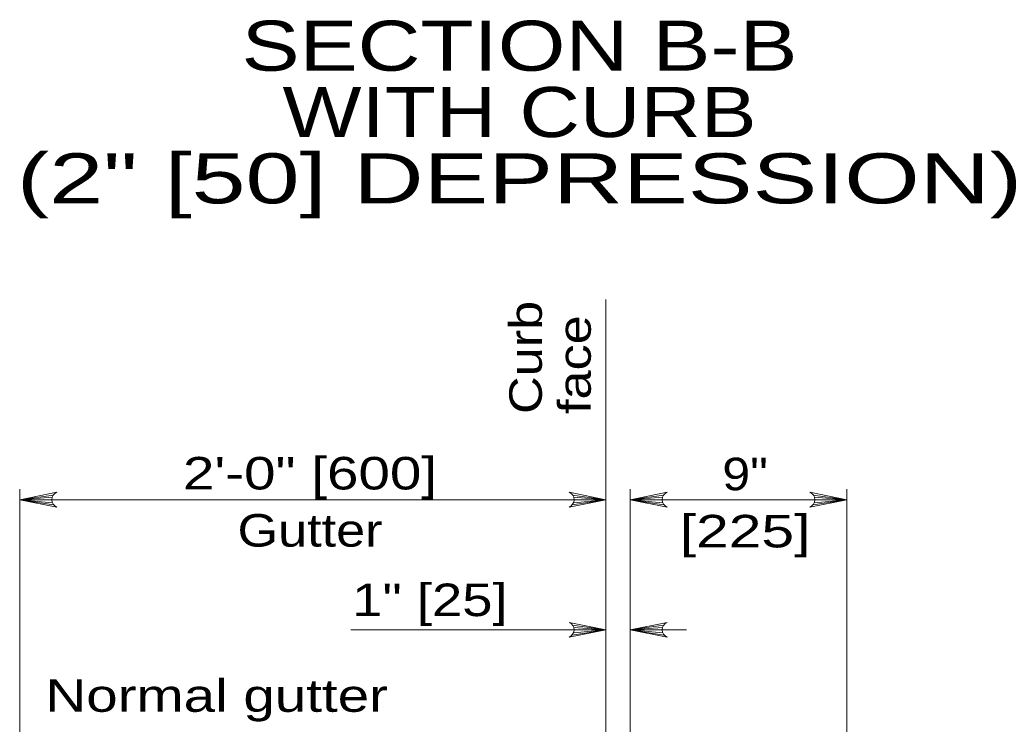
# Model space of a CAD drawing. Extents: x 1352.5 to 1386.5, y 735.9 to 779.9.
# Drawn here: x 1375.673 to 1380.45, y 765.011 to 768.387 of the extents above; entities that cross this region are included whole.
import ezdxf
from ezdxf.enums import TextEntityAlignment as Align

# ---------------------------------------------------------------- set-up
doc = ezdxf.new("R2010")
doc.units = 0
doc.header["$LTSCALE"] = 0.062
doc.layers.add('1', color=7, linetype='Continuous', lineweight=13)

msp = doc.modelspace()

# ---------------------------------------------------------------- linework, layer by layer
at = {"layer": '1'}
for p, q in [((1378.48325, 763.18375), (1378.48325, 767.046)), ((1375.673, 763.15467), (1375.673, 766.13667)), ((1378.59942, 763.671), (1378.59942, 766.13667)), ((1379.63783, 763.77275), (1379.63783, 766.13667)), ((1375.83325, 766.10908), (1375.673, 766.08667)), ((1375.82783, 766.098), (1375.673, 766.08667)), ((1375.673, 766.08667), (1377.82875, 766.08667)), ((1375.82617, 766.08667), (1375.673, 766.08667)), ((1375.829, 766.07225), (1375.673, 766.08667)), ((1375.83517, 766.06192), (1375.673, 766.08667)), ((1377.82875, 766.08667), (1378.48325, 766.08667)), ((1378.32108, 766.06192), (1378.48325, 766.08667)), ((1378.323, 766.10908), (1378.48325, 766.08667)), ((1378.32725, 766.07225), (1378.48325, 766.08667)), ((1378.32842, 766.098), (1378.48325, 766.08667)), ((1378.33008, 766.08667), (1378.48325, 766.08667)), ((1378.75967, 766.10908), (1378.59942, 766.08667)), ((1378.75425, 766.098), (1378.59942, 766.08667)), ((1378.59942, 766.08667), (1379.63783, 766.08667)), ((1378.75258, 766.08667), (1378.59942, 766.08667)), ((1378.75542, 766.07225), (1378.59942, 766.08667)), ((1378.76158, 766.06192), (1378.59942, 766.08667)), ((1379.47567, 766.06192), (1379.63783, 766.08667)), ((1379.47758, 766.10908), (1379.63783, 766.08667)), ((1379.48183, 766.07225), (1379.63783, 766.08667)), ((1379.483, 766.098), (1379.63783, 766.08667)), ((1379.48467, 766.08667), (1379.63783, 766.08667)), ((1378.48325, 765.46267), (1377.25958, 765.46267)), ((1378.32108, 765.43783), (1378.48325, 765.46267)), ((1378.323, 765.48508), (1378.48325, 765.46267)), ((1378.32725, 765.44825), (1378.48325, 765.46267)), ((1378.32842, 765.474), (1378.48325, 765.46267)), ((1378.33008, 765.46267), (1378.48325, 765.46267)), ((1378.75967, 765.48508), (1378.59942, 765.46267)), ((1378.75425, 765.474), (1378.59942, 765.46267)), ((1378.75258, 765.46267), (1378.59942, 765.46267)), ((1378.75542, 765.44825), (1378.59942, 765.46267)), ((1378.76158, 765.43783), (1378.59942, 765.46267)), ((1378.59942, 765.46267), (1378.86958, 765.46267))]:
    msp.add_line(p, q, dxfattribs=at)
for points in [[(1375.85, 766.05125), (1375.673, 766.08667), (1375.85, 766.12208)], [(1378.30625, 766.05125), (1378.48325, 766.08667), (1378.30625, 766.12208)], [(1378.77642, 766.05125), (1378.59942, 766.08667), (1378.77642, 766.12208)], [(1379.46083, 766.05125), (1379.63783, 766.08667), (1379.46083, 766.12208)], [(1378.30625, 765.42725), (1378.48325, 765.46267), (1378.30625, 765.498)], [(1378.77642, 765.42725), (1378.59942, 765.46267), (1378.77642, 765.498)]]:
    msp.add_lwpolyline(points, dxfattribs=at)
for centre, start, end in [((1375.86432, 766.08669), 112.08782, 247.91395), ((1378.29194, 766.08669), 292.08605, 67.91218), ((1378.79072, 766.08669), 112.08782, 247.91395), ((1379.44653, 766.08669), 292.08605, 67.91218), ((1378.29194, 765.46267), 292.08605, 67.91218), ((1378.79072, 765.46267), 112.08782, 247.91395)]:
    msp.add_arc(centre, 0.0382, start, end, dxfattribs=at)

# ---------------------------------------------------------------- texts
for s, height, width, p in [('SECTION B-B', 0.24, 1.3, (1378.06871, 768.14333)), ('WITH CURB', 0.24, 1.25, (1378.06875, 767.82533)), ('(2" [50] DEPRESSION)', 0.24, 1.45, (1378.06875, 767.50733)), ('2\'-0" [600]', 0.156, 1.3, (1377.06417, 766.13558)), ('9"', 0.156, 1.15, (1379.15058, 766.13183)), ('Gutter', 0.156, 1.2, (1377.06417, 765.86158)), ('[225]', 0.156, 1.35, (1379.15058, 765.85783))]:
    msp.add_text(s, height=height, dxfattribs=dict(at, width=width)).set_placement(p, align=Align.CENTER)
at = {"layer": '1', "width": 1.2}
for s, p in [('Curb', (1378.17583, 766.4975)), ('face', (1378.4105, 766.4975))]:
    msp.add_text(s, height=0.156, rotation=90, dxfattribs=at).set_placement(p)
at = {"layer": '1'}
for s, width, p in [('1" [25]', 1.25, (1377.26658, 765.52842)), ('Normal gutter', 1.3, (1375.79517, 765.0695))]:
    msp.add_text(s, height=0.156, dxfattribs=dict(at, width=width)).set_placement(p)

doc.saveas('drawing.dxf')
